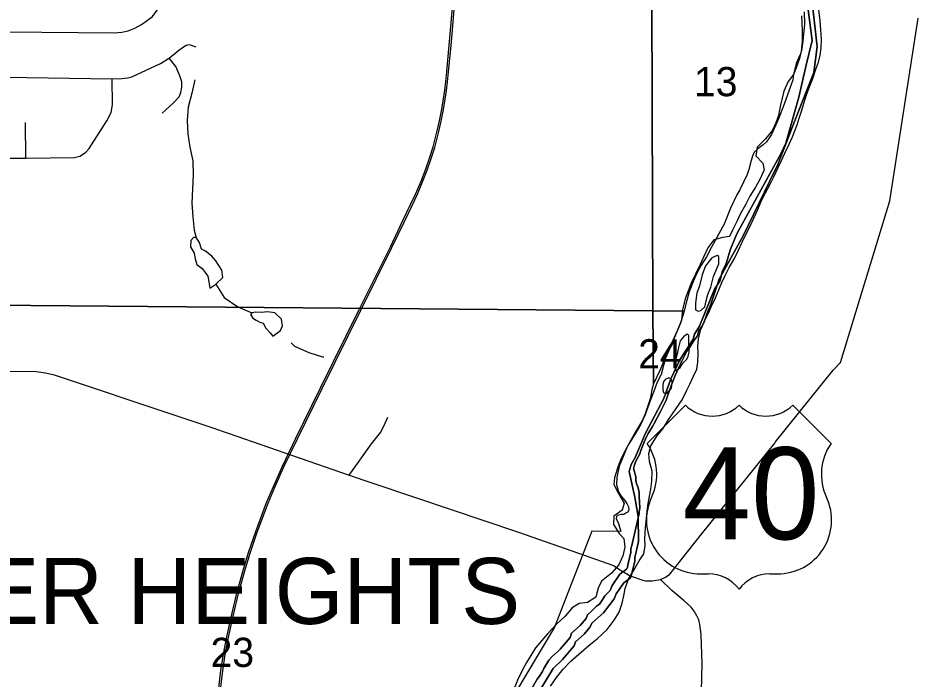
# Model space of a CAD drawing. Extents: x -38.1 to 35.9, y -2.7 to 28.5.
# Drawn here: x 9.239 to 10.521, y 14.335 to 15.282 of the extents above; entities that cross this region are included whole.
import ezdxf

# ---------------------------------------------------------------- set-up
doc = ezdxf.new("R2010")
doc.units = 0
for name, color, linetype in [('GM_P_County_Alignment', 7, 'Continuous'), ('GM_X_City_Street', 7, 'Continuous'), ('GM_X_Corporation', 7, 'Continuous'), ('GM_X_Interstate_Location', 7, 'Continuous'), ('GM_X_Major_River', 7, 'Continuous'), ('GM_X_Minor_River', 7, 'Continuous'), ('GM_X_Section', 7, 'Continuous'), ('GM_X_Township_Road', 7, 'Continuous'), ('GM_X_Township_Subdivision', 7, 'Continuous'), ('GM_X_US_Route', 7, 'Continuous'), ('SC_Scratch10', 7, 'Continuous')]:
    doc.layers.add(name, color=color, linetype=linetype)

msp = doc.modelspace()

# ---------------------------------------------------------------- linework, layer by layer
at = {"layer": 'GM_X_City_Street'}
msp.add_line((9.2504, 15.0815), (9.2495, 15.1325), dxfattribs=at)
for points in [[(9.1541, 15.2534), (9.1735, 15.254), (9.1838, 15.2561), (9.1964, 15.26), (9.2043, 15.2616), (9.2217, 15.2622), (9.3768, 15.2609), (9.3879, 15.2618), (9.3968, 15.2636), (9.4066, 15.2674), (9.416, 15.273), (9.4311, 15.2838), (9.4447, 15.3013), (9.4494, 15.311), (9.453, 15.3212), (9.4554, 15.33), (9.4555, 15.4144), (9.4554, 15.4474), (9.455, 15.4534), (9.4521, 15.4586), (9.4468, 15.4649), (9.4392, 15.4696)], [(9.154, 15.1979), (9.221, 15.1973), (9.3732, 15.195), (9.3741, 15.195), (9.3876, 15.1955), (9.3964, 15.1964), (9.4022, 15.1978), (9.4432, 15.2169), (9.4545, 15.2239), (9.4557, 15.2248), (9.4697, 15.2363), (9.479, 15.2428), (9.4843, 15.244), (9.4939, 15.2409)], [(9.4455, 15.146), (9.4614, 15.1603), (9.47, 15.1694), (9.4724, 15.1756), (9.4738, 15.1829), (9.4738, 15.1907), (9.4708, 15.1993), (9.4651, 15.2125), (9.4557, 15.2248)], [(9.1974, 15.0811), (9.2504, 15.0815), (9.3197, 15.0823), (9.3276, 15.0843), (9.3355, 15.0894), (9.3411, 15.095), (9.3665, 15.135), (9.3727, 15.1468), (9.3743, 15.1579), (9.3741, 15.195)], [(9.7137, 14.6269), (9.7455, 14.6718), (9.7588, 14.6888), (9.7651, 14.7016), (9.769, 14.7101)], [(10.218, 14.2978), (10.2197, 14.3568), (10.2181, 14.3989), (10.2162, 14.4129), (10.2149, 14.4195), (10.212, 14.4254), (10.2081, 14.4323), (10.2036, 14.4378), (10.1939, 14.4468), (10.1761, 14.4619), (10.1598, 14.4777)]]:
    msp.add_lwpolyline(points, dxfattribs=at)
at = {"layer": 'GM_X_Corporation'}
for points in [[(9.5223, 14.2845), (9.5299, 14.347), (9.5336, 14.3705), (9.5373, 14.3906), (9.542, 14.4127), (9.5453, 14.4276), (9.5526, 14.4581), (9.5613, 14.489), (9.5693, 14.5161), (9.5796, 14.5461), (9.5952, 14.588), (9.605, 14.611), (9.6179, 14.6401), (9.6371, 14.6803), (9.6726, 14.7521), (9.728, 14.8645), (9.7727, 14.9544), (9.7907, 14.9918), (9.8017, 15.0147), (9.8093, 15.0309), (9.8166, 15.0482), (9.823, 15.0648), (9.829, 15.0829), (9.8338, 15.0974), (9.8393, 15.1184), (9.843, 15.1347), (9.8463, 15.1513), (9.8487, 15.1664), (9.8507, 15.1788), (9.852, 15.1911), (9.8537, 15.2054), (9.8571, 15.2432), (9.8651, 15.3349)], [(9.5248, 14.2842), (9.5323, 14.3467), (9.536, 14.3701), (9.5397, 14.3901), (9.5444, 14.4122), (9.5477, 14.427), (9.555, 14.4575), (9.5637, 14.4883), (9.5717, 14.5153), (9.5819, 14.5453), (9.5975, 14.5871), (9.6073, 14.61), (9.6201, 14.6391), (9.6394, 14.6792), (9.6748, 14.751), (9.7302, 14.8634), (9.7749, 14.9533), (9.7929, 14.9907), (9.8039, 15.0136), (9.8116, 15.0299), (9.8189, 15.0473), (9.8253, 15.064), (9.8314, 15.0821), (9.8362, 15.0967), (9.8417, 15.1178), (9.8454, 15.1342), (9.8488, 15.1509), (9.8512, 15.166), (9.8532, 15.1785), (9.8545, 15.1908), (9.8562, 15.2051), (9.8596, 15.243), (9.8676, 15.3347)]]:
    msp.add_lwpolyline(points, dxfattribs=at)
at = {"layer": 'GM_X_Interstate_Location'}
for p, q in [((10.1956, 14.7274), (10.1406, 14.6724)), ((10.4043, 14.6724), (10.3494, 14.7274)), ((10.2175, 14.4857), (10.2285, 14.4857)), ((10.3164, 14.4857), (10.3274, 14.4857))]:
    msp.add_line(p, q, dxfattribs=at)
for centre, radius, start, end in [((10.234, 14.7666), 0.0549, 225.573, 314.427), ((10.3109, 14.7666), 0.0549, 225.573, 314.427), ((10.0776, 14.6283), 0.0769, 334.5471, 35.0009), ((10.4673, 14.6283), 0.0769, 144.9991, 205.4529), ((10.2167, 14.5626), 0.0769, 154.8319, 270.6383), ((10.3282, 14.5626), 0.0769, 269.3617, 25.1681), ((10.2285, 14.4307), 0.0549, 36.8699, 90), ((10.3164, 14.4307), 0.0549, 90, 143.1301)]:
    msp.add_arc(centre, radius, start, end, dxfattribs=at)
at = {"layer": 'GM_X_Major_River'}
for points in [[(10.3248, 14.6747), (10.4074, 14.7775), (10.4179, 14.7887), (10.4888, 15.0203), (10.5291, 15.2821)], [(9.1971, 14.7761), (9.2648, 14.7755), (9.2782, 14.7739), (9.2888, 14.7713)], [(9.2888, 14.7713), (9.292, 14.7705), (9.4651, 14.7127), (9.5183, 14.6948)], [(9.5183, 14.6948), (9.5346, 14.6893), (9.5401, 14.6874)], [(9.5401, 14.6874), (9.7137, 14.6269), (9.7461, 14.616), (9.8101, 14.5945)], [(10.1346, 14.4766), (10.1378, 14.4755), (10.1481, 14.4757), (10.1598, 14.4777), (10.1672, 14.4809), (10.173, 14.485), (10.2185, 14.5424), (10.3235, 14.6731), (10.3248, 14.6747)], [(9.8101, 14.5945), (9.9565, 14.5452), (10.0424, 14.5153), (10.0927, 14.4974), (10.102, 14.4916), (10.1037, 14.4906), (10.1114, 14.4858)], [(10.1114, 14.4858), (10.1156, 14.4832), (10.118, 14.4823), (10.1346, 14.4766)]]:
    msp.add_lwpolyline(points, dxfattribs=at)
at = {"layer": 'GM_X_Section'}
for points in [[(9.4925, 15.1937), (9.4879, 15.1744), (9.483, 15.1542), (9.4815, 15.1352), (9.4826, 15.1162), (9.4853, 15.0969), (9.4895, 15.0775), (9.4898, 15.0577), (9.4883, 15.0167), (9.4895, 14.9973), (9.4914, 14.978), (9.4944, 14.9677)], [(9.5226, 14.9008), (9.5344, 14.8815), (9.5542, 14.8682), (9.5743, 14.8598)], [(9.6303, 14.8165), (9.6354, 14.8118), (9.6559, 14.8027), (9.6753, 14.7966), (9.6772, 14.7966)], [(10.1361, 14.5485), (10.1362, 14.5489)]]:
    msp.add_lwpolyline(points, dxfattribs=at)
at = {"layer": 'GM_X_Township_Road'}
for points in [[(10.1385, 14.5509), (10.1408, 14.5756), (10.1421, 14.5865), (10.1442, 14.5971), (10.1458, 14.607), (10.1472, 14.6183), (10.1478, 14.6328), (10.1442, 14.6465), (10.1429, 14.6583), (10.1461, 14.6692), (10.1546, 14.6827), (10.1631, 14.6936), (10.1717, 14.7071), (10.1822, 14.7225), (10.1907, 14.7349), (10.197, 14.7477), (10.2017, 14.7575), (10.2072, 14.7688), (10.2119, 14.779), (10.2136, 14.7888), (10.2138, 14.8017), (10.2136, 14.8112), (10.2141, 14.8222), (10.2178, 14.8358), (10.2221, 14.846), (10.2287, 14.8592), (10.2331, 14.869), (10.2386, 14.881), (10.2437, 14.8927), (10.248, 14.9029), (10.2527, 14.913), (10.2582, 14.9247), (10.2664, 14.9383), (10.2715, 14.9496), (10.277, 14.9609), (10.2825, 14.9729), (10.2884, 14.9838), (10.2935, 14.9955), (10.2994, 15.0079), (10.3037, 15.0181), (10.3104, 15.0317), (10.317, 15.0441), (10.3221, 15.0546), (10.3284, 15.0678), (10.3335, 15.078), (10.3379, 15.0885), (10.3441, 15.1013), (10.3492, 15.1119), (10.3556, 15.1289), (10.3588, 15.1387), (10.362, 15.1489), (10.3652, 15.1598), (10.3688, 15.1704), (10.3727, 15.181), (10.3783, 15.1953), (10.3822, 15.2074), (10.3862, 15.2191), (10.3886, 15.2289), (10.3903, 15.2395), (10.3905, 15.252), (10.3896, 15.2653), (10.3887, 15.2782), (10.3868, 15.2941)], [(10.3618, 15.2855), (10.3624, 15.2752), (10.363, 15.2627), (10.3628, 15.249), (10.3614, 15.2346), (10.3593, 15.2241), (10.3542, 15.2109), (10.3503, 15.201), (10.3429, 15.1913), (10.3366, 15.1774), (10.3342, 15.1675), (10.3313, 15.1554), (10.3288, 15.1426), (10.3253, 15.132), (10.3201, 15.1207), (10.3097, 15.1087), (10.2985, 15.0971), (10.2964, 15.0846), (10.3065, 15.0742), (10.3083, 15.0647), (10.3027, 15.0519), (10.2961, 15.0399), (10.2879, 15.0267), (10.2817, 15.0143), (10.2746, 15.0019), (10.2699, 14.9917), (10.2636, 14.9789), (10.2589, 14.9691), (10.2494, 14.9674), (10.2361, 14.9645), (10.2276, 14.9529), (10.2213, 14.9394), (10.2165, 14.9288), (10.2099, 14.9152), (10.2048, 14.9047), (10.1953, 14.8798), (10.1916, 14.8639), (10.1899, 14.8492), (10.1839, 14.8341), (10.1776, 14.8198), (10.1721, 14.8066), (10.167, 14.7945), (10.1642, 14.7843), (10.1606, 14.7714), (10.1551, 14.7601), (10.1499, 14.7458), (10.1456, 14.7349), (10.1412, 14.7232), (10.1372, 14.7126), (10.1317, 14.7002), (10.1235, 14.6863), (10.1162, 14.6746), (10.1091, 14.6622), (10.1029, 14.6502), (10.0981, 14.6373), (10.0941, 14.6234), (10.0928, 14.6135), (10.0998, 14.6009), (10.108, 14.5871), (10.1051, 14.5769), (10.0932, 14.5684), (10.0923, 14.5562), (10.1008, 14.5436)], [(10.241, 14.9417), (10.2334, 14.9384), (10.2245, 14.9268), (10.2197, 14.914), (10.2157, 14.8985), (10.2121, 14.8879), (10.21, 14.8739), (10.2102, 14.864), (10.214, 14.8621), (10.2178, 14.8628), (10.2236, 14.8684), (10.2252, 14.8771), (10.2276, 14.8861)], [(10.2276, 14.8861), (10.232, 14.8963), (10.2356, 14.9118), (10.2435, 14.9299), (10.2437, 14.9405), (10.241, 14.9417)], [(10.1983, 14.8293), (10.1929, 14.8252), (10.1879, 14.8196), (10.1858, 14.8101), (10.1838, 14.8007), (10.181, 14.7905), (10.1797, 14.7829), (10.1819, 14.7764), (10.188, 14.7813), (10.1923, 14.788), (10.1977, 14.7932), (10.1997, 14.7974)], [(10.1997, 14.7974), (10.2009, 14.8031), (10.2007, 14.8141), (10.2005, 14.827), (10.1983, 14.8293)], [(10.1767, 14.7606), (10.1753, 14.7648), (10.1719, 14.7663), (10.1665, 14.7641), (10.1638, 14.7604), (10.163, 14.7543), (10.1633, 14.749), (10.1643, 14.7456), (10.167, 14.744), (10.1696, 14.7444)], [(10.1696, 14.7444), (10.1754, 14.7519), (10.1763, 14.7553), (10.1767, 14.7606)], [(10.0022, 14.3249), (10.0108, 14.3373), (10.0202, 14.3489), (10.0314, 14.3604), (10.043, 14.3705), (10.0569, 14.3831), (10.0697, 14.3931), (10.0832, 14.4061), (10.0934, 14.4192), (10.1004, 14.4305), (10.1049, 14.4437), (10.1073, 14.4543), (10.1094, 14.4645), (10.1139, 14.4781), (10.1214, 14.4908), (10.1292, 14.5043), (10.1359, 14.5141), (10.138, 14.5262), (10.1374, 14.5361), (10.1385, 14.5509)], [(10.1008, 14.5436), (10.1074, 14.5363), (10.1087, 14.5241), (10.1058, 14.5113), (10.0999, 14.4985), (10.0894, 14.4865), (10.0751, 14.475), (10.0707, 14.4653), (10.067, 14.4524), (10.0551, 14.4447), (10.0433, 14.443), (10.0333, 14.4368), (10.0232, 14.4248), (10.0108, 14.4133), (9.998, 14.3995), (9.9891, 14.3894), (9.9809, 14.3797), (9.9738, 14.3684), (9.968, 14.3587), (9.9616, 14.347), (9.9549, 14.3335), (9.9479, 14.3157)]]:
    msp.add_lwpolyline(points, dxfattribs=at)
at = {"layer": 'GM_X_US_Route'}
for points in [[(9.1505, 15.8719), (9.1857, 15.8712), (10.0492, 15.8683), (10.0548, 15.8626), (10.0625, 15.8533), (10.0673, 15.8468), (10.0758, 15.8357), (10.0814, 15.8287), (10.0851, 15.8249), (10.0967, 15.816), (10.1026, 15.8105), (10.1237, 15.7848), (10.1304, 15.7756), (10.1459, 15.7537), (10.1489, 14.8625), (9.1455, 14.871)], [(10.1489, 14.8625), (10.1936, 14.862), (10.1884, 14.8447), (10.1793, 14.8234), (10.165, 14.7918), (10.1588, 14.777), (10.1496, 14.758)]]:
    msp.add_lwpolyline(points, close=True, dxfattribs=at)
for points in [[(10.3656, 15.2909), (10.3664, 15.2735), (10.3637, 15.2489), (10.3619, 15.2357), (10.3607, 15.2308), (10.3575, 15.2244), (10.3544, 15.2169), (10.3507, 15.2011), (10.3494, 15.1935), (10.3462, 15.1841), (10.337, 15.1589), (10.329, 15.1379), (10.3188, 15.1153), (10.3153, 15.1093), (10.3118, 15.1049), (10.3071, 15.1004), (10.2994, 15.0945), (10.2941, 15.09), (10.2917, 15.0844), (10.2897, 15.078), (10.2864, 15.0652), (10.284, 15.0577), (10.2737, 15.0359), (10.2694, 15.0288), (10.2604, 15.0096), (10.2509, 14.9867), (10.2328, 14.9537), (10.2257, 14.9398), (10.2183, 14.9278), (10.212, 14.9166), (10.2073, 14.9053), (10.2009, 14.8899), (10.1961, 14.8722), (10.1936, 14.862), (10.1489, 14.8625), (10.1459, 15.7537)], [(9.9759, 14.3224), (9.9831, 14.3348), (9.9862, 14.339), (9.9908, 14.3458), (9.9927, 14.35), (10, 14.3621), (10.0046, 14.3674), (10.0138, 14.3753), (10.0159, 14.3779), (10.0302, 14.3946), (10.0321, 14.4007), (10.0447, 14.4116), (10.0531, 14.4218), (10.0554, 14.4271), (10.06, 14.4313), (10.0673, 14.4385), (10.0682, 14.4392), (10.0722, 14.4422), (10.0772, 14.4494), (10.0803, 14.454), (10.0875, 14.4619), (10.0906, 14.4691), (10.1017, 14.485), (10.1061, 14.4886), (10.1067, 14.4891), (10.1086, 14.4904), (10.1113, 14.4922), (10.1113, 14.4923), (10.1115, 14.4928), (10.1124, 14.4948), (10.1136, 14.5009), (10.1152, 14.5081), (10.1163, 14.513), (10.1175, 14.5157), (10.1175, 14.5214), (10.1187, 14.5263), (10.1195, 14.5305), (10.1238, 14.5491), (10.1292, 14.5722), (10.1294, 14.5742), (10.13, 14.5802), (10.1295, 14.5964), (10.1292, 14.6021), (10.128, 14.6089), (10.1258, 14.6138), (10.1246, 14.6188), (10.1243, 14.6248), (10.1212, 14.6369), (10.1216, 14.6381), (10.1228, 14.6419), (10.1243, 14.6472), (10.13, 14.6574), (10.1319, 14.6623), (10.1361, 14.6733), (10.1395, 14.6809), (10.1421, 14.6868), (10.1485, 14.6968), (10.1506, 14.701), (10.1597, 14.7185), (10.1638, 14.7257), (10.1678, 14.7347), (10.1706, 14.7416), (10.1733, 14.7491), (10.1756, 14.7567), (10.1809, 14.77), (10.1881, 14.7855), (10.1938, 14.7973), (10.1976, 14.8045), (10.2018, 14.8105), (10.2018, 14.8106), (10.2071, 14.8189), (10.2128, 14.8268), (10.215, 14.834), (10.2196, 14.8405), (10.2198, 14.8409), (10.2219, 14.8454), (10.2287, 14.8644), (10.2305, 14.8682), (10.2319, 14.8722), (10.244, 14.9079), (10.2783, 14.9701), (10.3165, 15.0487), (10.328, 15.0724), (10.3289, 15.0746), (10.3521, 15.1337), (10.377, 15.197), (10.3798, 15.2042), (10.3843, 15.2415), (10.3839, 15.245), (10.3784, 15.2965)], [(10.3784, 15.2965), (10.3839, 15.245), (10.3843, 15.2415), (10.3798, 15.2042), (10.377, 15.197), (10.3521, 15.1337), (10.3289, 15.0746), (10.328, 15.0724), (10.3165, 15.0487), (10.2783, 14.9701), (10.244, 14.9079), (10.2319, 14.8722), (10.2305, 14.8682), (10.2287, 14.8644), (10.2219, 14.8454), (10.2198, 14.8409), (10.2196, 14.8405), (10.215, 14.834), (10.2128, 14.8268), (10.2071, 14.8189), (10.2018, 14.8106), (10.1976, 14.8045), (10.1938, 14.7973), (10.1881, 14.7855), (10.1809, 14.77), (10.1756, 14.7567), (10.1733, 14.7491), (10.1706, 14.7416), (10.1678, 14.7347), (10.1638, 14.7257), (10.1597, 14.7185), (10.1506, 14.701), (10.1485, 14.6968), (10.1421, 14.6868), (10.1395, 14.6809), (10.1361, 14.6733), (10.1319, 14.6623), (10.13, 14.6574), (10.1243, 14.6472), (10.1228, 14.6419), (10.1216, 14.6381), (10.1212, 14.6369), (10.1243, 14.6248), (10.1246, 14.6188), (10.1258, 14.6138), (10.128, 14.6089), (10.1292, 14.6021), (10.1295, 14.5964), (10.13, 14.5802), (10.1294, 14.5742), (10.1292, 14.5722), (10.1238, 14.5491), (10.1195, 14.5305), (10.1187, 14.5263), (10.1175, 14.5214), (10.1175, 14.5157), (10.1163, 14.513), (10.1152, 14.5081), (10.1136, 14.5009), (10.1124, 14.4948), (10.1115, 14.4928), (10.1113, 14.4923), (10.1113, 14.4922), (10.1086, 14.4904), (10.1067, 14.4891), (10.1061, 14.4886), (10.1017, 14.485), (10.0906, 14.4691), (10.0875, 14.4619), (10.0803, 14.454), (10.0772, 14.4494), (10.0722, 14.4422), (10.0682, 14.4392), (10.0673, 14.4385), (10.06, 14.4313), (10.0554, 14.4271), (10.0531, 14.4218), (10.0447, 14.4116), (10.0321, 14.4007), (10.0302, 14.3946), (10.0159, 14.3779), (10.0138, 14.3753), (10.0046, 14.3674), (10, 14.3621), (9.9927, 14.35), (9.9908, 14.3458), (9.9862, 14.339), (9.9831, 14.3348), (9.9759, 14.3224)], [(9.9816, 14.3101), (10.0058, 14.3498), (10.0195, 14.363), (10.036, 14.3823), (10.0379, 14.3884), (10.0505, 14.3993), (10.0589, 14.4095), (10.0612, 14.4148), (10.078, 14.4299), (10.0933, 14.4496), (10.0964, 14.4568), (10.1075, 14.4727), (10.117, 14.4798), (10.1178, 14.4829), (10.1232, 14.5033), (10.1233, 14.509), (10.1283, 14.5318), (10.1278, 14.5677), (10.123, 14.5957), (10.115, 14.6321), (10.118, 14.6423), (10.1237, 14.6525), (10.1382, 14.687), (10.1644, 14.7367), (10.1746, 14.7651), (10.1875, 14.7923), (10.2065, 14.8219), (10.2088, 14.8291), (10.2156, 14.8405), (10.2373, 14.8935), (10.2448, 14.9049), (10.2486, 14.92), (10.254, 14.9306), (10.26, 14.9511), (10.2695, 14.9731), (10.3329, 15.0883), (10.3394, 15.103), (10.358, 15.1686), (10.3683, 15.2125), (10.3774, 15.25), (10.371, 15.2977)], [(10.371, 15.2977), (10.3774, 15.25), (10.3683, 15.2125), (10.358, 15.1686), (10.3394, 15.103), (10.3329, 15.0883), (10.2695, 14.9731), (10.26, 14.9511), (10.254, 14.9306), (10.2486, 14.92), (10.2448, 14.9049), (10.2373, 14.8935), (10.2156, 14.8405), (10.2088, 14.8291), (10.2065, 14.8219), (10.1875, 14.7923), (10.1746, 14.7651), (10.1644, 14.7367), (10.1382, 14.687), (10.1237, 14.6525), (10.118, 14.6423), (10.115, 14.6321), (10.123, 14.5957), (10.1278, 14.5677), (10.1283, 14.5318), (10.1233, 14.509), (10.1232, 14.5033), (10.1178, 14.4829), (10.117, 14.4798), (10.1075, 14.4727), (10.0964, 14.4568), (10.0933, 14.4496), (10.078, 14.4299), (10.0612, 14.4148), (10.0589, 14.4095), (10.0505, 14.3993), (10.0379, 14.3884), (10.036, 14.3823), (10.0195, 14.363), (10.0058, 14.3498), (9.9816, 14.3101)], [(9.1455, 14.871), (10.1489, 14.8625), (10.1496, 14.758), (10.1476, 14.7497), (10.1455, 14.738), (10.1415, 14.7263), (10.1378, 14.715), (10.1339, 14.706), (10.1241, 14.6891), (10.1123, 14.6678), (10.1052, 14.6516), (10.1008, 14.6399), (10.0975, 14.6237), (10.0969, 14.6135), (10.098, 14.6082), (10.0998, 14.6032), (10.1031, 14.5975), (10.1086, 14.5909), (10.1116, 14.5863), (10.1138, 14.5818), (10.1144, 14.5776), (10.1132, 14.5738), (10.1102, 14.5724), (10.1075, 14.5709), (10.1037, 14.5706), (10.0995, 14.5699), (10.0976, 14.5692), (10.0968, 14.5673), (10.0964, 14.565), (10.0997, 14.5578), (10.1028, 14.5462), (10.0616, 14.547), (10.0615, 14.5468), (10.0079, 14.409), (9.8343, 14.1188)]]:
    msp.add_lwpolyline(points, dxfattribs=at)
at = {"layer": 'SC_Scratch10'}
for points in [[(9.5226, 14.9008), (9.5326, 14.9102), (9.5309, 14.9208), (9.5224, 14.9342), (9.5168, 14.9408), (9.5078, 14.9478), (9.5021, 14.9509), (9.4989, 14.9604), (9.4944, 14.9677), (9.4906, 14.9674), (9.4867, 14.9633), (9.4862, 14.9542), (9.4914, 14.9454), (9.4928, 14.937), (9.4953, 14.929), (9.5028, 14.9232)], [(9.5028, 14.9232), (9.5073, 14.9174), (9.511, 14.9124), (9.5121, 14.9071), (9.5141, 14.8949), (9.5226, 14.9008)], [(9.6153, 14.8344), (9.6181, 14.8412), (9.6167, 14.8504), (9.607, 14.8596), (9.5964, 14.8613), (9.588, 14.8603), (9.5797, 14.8608), (9.5743, 14.8598), (9.572, 14.8575), (9.5757, 14.8522), (9.5802, 14.8491), (9.5855, 14.8463), (9.5904, 14.8447)], [(9.5904, 14.8447), (9.5941, 14.8378), (9.6005, 14.8309), (9.6042, 14.8263), (9.6153, 14.8344)]]:
    msp.add_lwpolyline(points, dxfattribs=at)

# ---------------------------------------------------------------- texts
at = {"layer": 'GM_P_County_Alignment'}
for s in ['0', '/']:
    msp.add_text(s, height=0.000189, dxfattribs=at).set_placement((10.2724, 14.6))
msp.add_text('40', height=0.000189, rotation=0, dxfattribs=at).set_placement((10.2333, 14.5608))
at = {"layer": 'GM_X_Interstate_Location'}
msp.add_text('40', height=0.13184, dxfattribs=at).set_placement((10.1916, 14.5351))
at = {"layer": 'GM_X_Minor_River'}
for s, p in [('13', (10.2079, 15.1701)), ('24', (10.1279, 14.78)), ('23', (9.515, 14.3522))]:
    msp.add_text(s, height=0.04186, rotation=0, dxfattribs=at).set_placement(p)
at = {"layer": 'GM_X_Township_Subdivision'}
msp.add_text('HUBER HEIGHTS', height=0.094697, rotation=0, dxfattribs=at).set_placement((8.9174, 14.4138))

doc.saveas('drawing.dxf')
